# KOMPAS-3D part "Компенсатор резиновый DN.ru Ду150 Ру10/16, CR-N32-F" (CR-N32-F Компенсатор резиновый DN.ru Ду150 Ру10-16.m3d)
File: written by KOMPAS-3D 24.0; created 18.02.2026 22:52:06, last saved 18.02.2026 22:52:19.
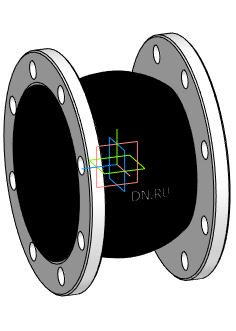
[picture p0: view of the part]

Document properties: Автор: DN.RU; Полное имя файла: D:\PROJECT CAD\DN.RU\...178(2)(ACTUALE). CR-N32-F Компенсатор резиновый DN.ru Ру10-16\CR-N32-F Компенсатор резиновый DN.ru Ру10-16\DN150\CR-N32-F Компенсатор резиновый DN.ru Ду150 Ру10-16 (2d).m3d

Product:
- Body: Твердое тело2  | qty 1
    Масса: 29.199535
- Part/product: Компенсатор резиновый DN.ru Ду150 Ру10/16  | designation CR-N32-F
    Масса: 15
    Раздел спецификации: Прочие изделия
    Комментарий: D140-02396
    Примечание: D140-02381
    additional columns: Типовые

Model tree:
1. Твердое тело2  (labels: Твердое тело2)

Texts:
  CR-N32-F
